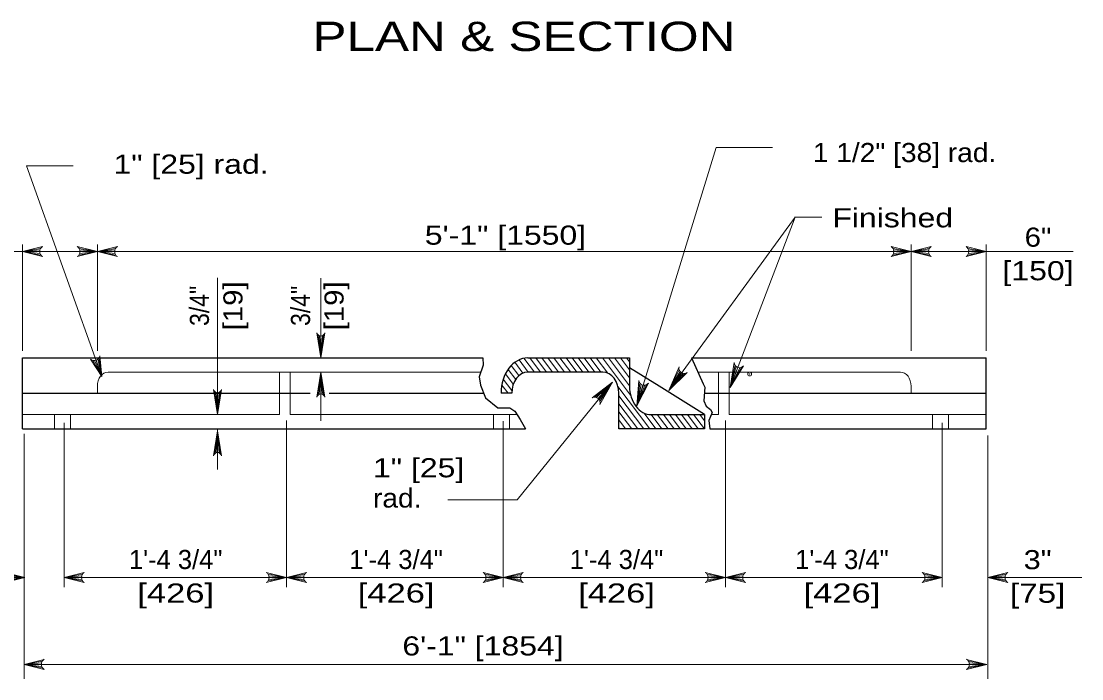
# Model space of a CAD drawing. Extents: x 1352.5 to 1386.5, y 735.9 to 779.9.
# Drawn here: x 1356.98 to 1365.64, y 745.48 to 750.85 of the extents above; entities that cross this region are included whole.
import ezdxf
from ezdxf.enums import TextEntityAlignment as Align

# ---------------------------------------------------------------- set-up
doc = ezdxf.new("R2010")
doc.units = 0
doc.header["$LTSCALE"] = 0.062
doc.header["$PDMODE"] = 32
doc.header["$PDSIZE"] = 0.031
doc.layers.add('1', color=7, linetype='Continuous', lineweight=13)

msp = doc.modelspace()

# ---------------------------------------------------------------- linework, layer by layer
at = {"layer": '1'}
for p, q in [((1362.27117, 747.83458), (1363.30317, 749.24783)), ((1356.99267, 748.15767), (1356.99267, 749.02575)), ((1357.60467, 748.15767), (1357.60467, 749.02575)), ((1364.24883, 748.15767), (1364.24883, 749.02575)), ((1364.86083, 748.15767), (1364.86083, 749.02575)), ((1357.14108, 748.99392), (1356.99267, 748.96792)), ((1357.136, 748.98108), (1356.99267, 748.96792)), ((1357.1345, 748.96792), (1356.99267, 748.96792)), ((1357.13717, 748.95125), (1356.99267, 748.96792)), ((1357.14283, 748.93925), (1356.99267, 748.96792)), ((1357.4545, 748.93925), (1357.60467, 748.96792)), ((1357.45625, 748.99392), (1357.60467, 748.96792)), ((1357.46017, 748.95125), (1357.60467, 748.96792)), ((1357.46125, 748.98108), (1357.60467, 748.96792)), ((1357.46275, 748.96792), (1357.60467, 748.96792)), ((1357.753, 748.99392), (1357.60467, 748.96792)), ((1357.748, 748.98108), (1357.60467, 748.96792)), ((1357.7465, 748.96792), (1357.60467, 748.96792)), ((1357.74908, 748.95125), (1357.60467, 748.96792)), ((1357.75475, 748.93925), (1357.60467, 748.96792)), ((1357.60467, 748.96792), (1359.55883, 748.96792)), ((1359.55883, 748.96792), (1361.28483, 748.96792)), ((1361.28483, 748.96792), (1362.64008, 748.96792)), ((1362.64008, 748.96792), (1364.24883, 748.96792)), ((1364.09867, 748.93925), (1364.24883, 748.96792)), ((1364.10042, 748.99392), (1364.24883, 748.96792)), ((1364.10433, 748.95125), (1364.24883, 748.96792)), ((1364.1055, 748.98108), (1364.24883, 748.96792)), ((1364.107, 748.96792), (1364.24883, 748.96792)), ((1364.39725, 748.99392), (1364.24883, 748.96792)), ((1364.39225, 748.98108), (1364.24883, 748.96792)), ((1364.24883, 748.96792), (1365.57108, 748.96792)), ((1364.39067, 748.96792), (1364.24883, 748.96792)), ((1364.39333, 748.95125), (1364.24883, 748.96792)), ((1364.399, 748.93925), (1364.24883, 748.96792)), ((1364.63833, 748.96792), (1364.86083, 748.96792)), ((1364.71067, 748.93925), (1364.86083, 748.96792)), ((1364.71242, 748.99392), (1364.86083, 748.96792)), ((1364.71633, 748.95125), (1364.86083, 748.96792)), ((1364.71742, 748.98108), (1364.86083, 748.96792)), ((1364.719, 748.96792), (1364.86083, 748.96792)), ((1358.58542, 748.75292), (1358.58542, 747.63708)), ((1359.42892, 748.09983), (1359.42892, 748.74983)), ((1359.40817, 748.28533), (1359.42892, 748.09983)), ((1359.41842, 748.27908), (1359.42892, 748.09983)), ((1359.45192, 748.28758), (1359.42892, 748.09983)), ((1359.44225, 748.28042), (1359.42892, 748.09983)), ((1359.42892, 748.27717), (1359.42892, 748.09983)), ((1357.567, 748.07975), (1357.64058, 747.94833)), ((1357.58075, 748.07925), (1357.64058, 747.94833)), ((1357.59367, 748.08217), (1357.64058, 747.94833)), ((1357.6085, 748.09017), (1357.64058, 747.94833)), ((1357.618, 748.0995), (1357.64058, 747.94833)), ((1361.01342, 748.06367), (1361.07958, 747.97617)), ((1361.04758, 748.08392), (1361.123, 747.98417)), ((1361.08742, 748.09675), (1361.1725, 747.98417)), ((1361.13442, 748.09983), (1361.22192, 747.98417)), ((1361.18392, 748.09983), (1361.27142, 747.98417)), ((1361.23333, 748.09983), (1361.32083, 747.98417)), ((1361.28283, 748.09983), (1361.37033, 747.98417)), ((1361.33233, 748.09983), (1361.41975, 747.98417)), ((1361.38175, 748.09983), (1361.46917, 747.98417)), ((1361.43117, 748.09983), (1361.51867, 747.98417)), ((1361.48067, 748.09983), (1361.56817, 747.98417)), ((1361.53008, 748.09983), (1361.61758, 747.98417)), ((1361.57958, 748.09983), (1361.667, 747.98417)), ((1361.629, 748.09983), (1361.7165, 747.98417)), ((1361.67842, 748.09983), (1361.77283, 747.975)), ((1361.728, 748.09983), (1361.95867, 747.7945)), ((1361.77733, 748.09983), (1361.9495, 747.872)), ((1361.82683, 748.09983), (1361.9495, 747.9375)), ((1361.87633, 748.09983), (1361.9495, 748.003)), ((1361.92575, 748.09983), (1361.9495, 748.06842)), ((1360.735, 747.98417), (1357.69208, 747.98417)), ((1359.09083, 747.63708), (1359.09083, 747.98417)), ((1359.17825, 747.63708), (1359.17825, 747.98417)), ((1359.406, 747.7965), (1359.42892, 747.98417)), ((1359.41558, 747.80358), (1359.42892, 747.98417)), ((1359.42892, 747.98417), (1359.42892, 747.58533)), ((1359.42892, 747.80683), (1359.42892, 747.98417)), ((1359.43942, 747.80492), (1359.42892, 747.98417)), ((1359.44975, 747.79867), (1359.42892, 747.98417)), ((1360.95808, 748.00617), (1361.02, 747.92417)), ((1360.98367, 748.03767), (1361.04625, 747.95483)), ((1362.355, 748.00208), (1362.27117, 747.83458)), ((1362.362, 747.98967), (1362.27117, 747.83458)), ((1362.37167, 747.98058), (1362.27117, 747.83458)), ((1362.38725, 747.97383), (1362.27117, 747.83458)), ((1362.40125, 747.97292), (1362.27117, 747.83458)), ((1364.16142, 747.98417), (1362.50875, 747.98417)), ((1362.67525, 747.63708), (1362.67525, 747.98417)), ((1362.76267, 747.63708), (1362.76267, 747.98417)), ((1362.8115, 748.03958), (1362.77, 747.85692)), ((1362.82125, 748.02917), (1362.77, 747.85692)), ((1362.83283, 748.02275), (1362.77, 747.85692)), ((1362.86333, 748.02233), (1362.77, 747.85692)), ((1362.84958, 748.01992), (1362.77, 747.85692)), ((1360.919, 747.92692), (1360.98917, 747.83408)), ((1360.93642, 747.96933), (1361.0005, 747.88458)), ((1361.6655, 747.77875), (1361.81117, 747.90058)), ((1361.67925, 747.77617), (1361.81117, 747.90058)), ((1361.69392, 747.76758), (1361.81117, 747.90058)), ((1361.7025, 747.7575), (1361.81117, 747.90058)), ((1361.70792, 747.74425), (1361.81117, 747.90058)), ((1362.03425, 747.89292), (1362.00858, 747.70742)), ((1357.60467, 747.8685), (1357.60467, 747.81058)), ((1358.56467, 747.82258), (1358.58542, 747.63708)), ((1358.57492, 747.81633), (1358.58542, 747.63708)), ((1358.60842, 747.82475), (1358.58542, 747.63708)), ((1358.59875, 747.81767), (1358.58542, 747.63708)), ((1358.58542, 747.81442), (1358.58542, 747.63708)), ((1360.90067, 747.82025), (1360.90792, 747.81058)), ((1360.9065, 747.878), (1360.95742, 747.81058)), ((1361.85517, 747.86608), (1362.11558, 747.52142)), ((1362.04483, 747.88342), (1362.00858, 747.70742)), ((1362.08742, 747.88017), (1362.00858, 747.70742)), ((1362.05692, 747.878), (1362.00858, 747.70742)), ((1362.07392, 747.87658), (1362.00858, 747.70742)), ((1364.24883, 747.8685), (1364.24883, 747.81058)), ((1361.86208, 747.79142), (1362.06608, 747.52142)), ((1361.86208, 747.726), (1362.01667, 747.52142)), ((1356.99267, 747.63708), (1359.09083, 747.63708)), ((1357.25492, 747.63708), (1357.25492, 747.52142)), ((1357.38608, 747.63708), (1357.38608, 747.52142)), ((1359.17825, 747.63708), (1361.03092, 747.63708)), ((1360.83933, 747.63708), (1360.83933, 747.52142)), ((1360.97042, 747.63708), (1360.97042, 747.52142)), ((1361.86208, 747.66058), (1361.96725, 747.52142)), ((1362.06842, 747.64925), (1362.165, 747.52142)), ((1362.12708, 747.63708), (1362.2145, 747.52142)), ((1362.1765, 747.63708), (1362.26392, 747.52142)), ((1362.226, 747.63708), (1362.31342, 747.52142)), ((1362.27542, 747.63708), (1362.36283, 747.52142)), ((1362.32483, 747.63708), (1362.41225, 747.52142)), ((1362.37433, 747.63708), (1362.46175, 747.52142)), ((1362.42383, 747.63708), (1362.51125, 747.52142)), ((1362.47325, 747.63708), (1362.56067, 747.52142)), ((1362.52275, 747.63708), (1362.5615, 747.58575)), ((1362.61733, 747.63708), (1362.67525, 747.63708)), ((1362.76267, 747.63708), (1364.86083, 747.63708)), ((1364.42367, 747.63708), (1364.42367, 747.52142)), ((1364.55483, 747.63708), (1364.55483, 747.52142)), ((1357.334, 746.22842), (1357.334, 747.57025)), ((1359.14808, 746.22842), (1359.14808, 747.5885)), ((1360.91842, 746.22842), (1360.91842, 747.58242)), ((1361.86208, 747.59517), (1361.91775, 747.52142)), ((1362.73242, 746.22842), (1362.73242, 747.5885)), ((1364.50275, 746.22842), (1364.50275, 747.57025)), ((1357.00617, 745.47992), (1357.00617, 747.47875)), ((1358.56467, 747.31983), (1358.58542, 747.50533)), ((1358.57492, 747.32608), (1358.58542, 747.50533)), ((1358.58542, 747.52142), (1358.58542, 747.18817)), ((1358.58542, 747.328), (1358.58542, 747.50533)), ((1358.59875, 747.32475), (1358.58542, 747.50533)), ((1358.60842, 747.31767), (1358.58542, 747.50533)), ((1361.86208, 747.52967), (1361.86833, 747.52142)), ((1364.87433, 745.47992), (1364.87433, 747.46658)), ((1356.86342, 746.333), (1357.01183, 746.30708)), ((1357.48242, 746.333), (1357.334, 746.30708)), ((1358.99967, 746.333), (1359.14808, 746.30708)), ((1359.2965, 746.333), (1359.14808, 746.30708)), ((1360.77, 746.333), (1360.91842, 746.30708)), ((1361.06683, 746.333), (1360.91842, 746.30708)), ((1362.58408, 746.333), (1362.73242, 746.30708)), ((1362.88083, 746.333), (1362.73242, 746.30708)), ((1364.35442, 746.333), (1364.50275, 746.30708)), ((1365.02275, 746.333), (1364.87433, 746.30708)), ((1356.24792, 746.30708), (1357.00283, 746.30708)), ((1356.86167, 746.27833), (1357.01183, 746.30708)), ((1356.86733, 746.29042), (1357.01183, 746.30708)), ((1356.86842, 746.32017), (1357.01183, 746.30708)), ((1356.87, 746.30708), (1357.01183, 746.30708)), ((1357.47742, 746.32017), (1357.334, 746.30708)), ((1357.47592, 746.30708), (1357.334, 746.30708)), ((1357.4785, 746.29042), (1357.334, 746.30708)), ((1357.48417, 746.27833), (1357.334, 746.30708)), ((1357.34392, 746.30708), (1364.09925, 746.30708)), ((1358.6425, 746.30708), (1359.14808, 746.30708)), ((1358.99792, 746.27833), (1359.14808, 746.30708)), ((1359.00358, 746.29042), (1359.14808, 746.30708)), ((1359.00467, 746.32017), (1359.14808, 746.30708)), ((1359.00625, 746.30708), (1359.14808, 746.30708)), ((1359.29142, 746.32017), (1359.14808, 746.30708)), ((1359.28992, 746.30708), (1359.14808, 746.30708)), ((1359.2925, 746.29042), (1359.14808, 746.30708)), ((1359.29825, 746.27833), (1359.14808, 746.30708)), ((1359.14808, 746.30708), (1359.50433, 746.30708)), ((1360.76825, 746.27833), (1360.91842, 746.30708)), ((1360.77392, 746.29042), (1360.91842, 746.30708)), ((1360.775, 746.32017), (1360.91842, 746.30708)), ((1360.77658, 746.30708), (1360.91842, 746.30708)), ((1361.06175, 746.32017), (1360.91842, 746.30708)), ((1361.06025, 746.30708), (1360.91842, 746.30708)), ((1361.06292, 746.29042), (1360.91842, 746.30708)), ((1361.06858, 746.27833), (1360.91842, 746.30708)), ((1362.58233, 746.27833), (1362.73242, 746.30708)), ((1362.588, 746.29042), (1362.73242, 746.30708)), ((1362.58908, 746.32017), (1362.73242, 746.30708)), ((1362.59058, 746.30708), (1362.73242, 746.30708)), ((1362.87583, 746.32017), (1362.73242, 746.30708)), ((1362.87433, 746.30708), (1362.73242, 746.30708)), ((1362.87692, 746.29042), (1362.73242, 746.30708)), ((1362.88258, 746.27833), (1362.73242, 746.30708)), ((1364.09925, 746.30708), (1364.50275, 746.30708)), ((1364.35267, 746.27833), (1364.50275, 746.30708)), ((1364.35833, 746.29042), (1364.50275, 746.30708)), ((1364.35942, 746.32017), (1364.50275, 746.30708)), ((1364.36092, 746.30708), (1364.50275, 746.30708)), ((1365.01775, 746.32017), (1364.87433, 746.30708)), ((1365.01617, 746.30708), (1364.87433, 746.30708)), ((1365.01883, 746.29042), (1364.87433, 746.30708)), ((1365.0245, 746.27833), (1364.87433, 746.30708)), ((1364.87433, 746.30708), (1365.64208, 746.30708)), ((1357.15458, 745.62367), (1357.00617, 745.59775)), ((1357.14958, 745.61083), (1357.00617, 745.59775)), ((1357.148, 745.59775), (1357.00617, 745.59775)), ((1357.15067, 745.58108), (1357.00617, 745.59775)), ((1357.15633, 745.56908), (1357.00617, 745.59775)), ((1357.00617, 745.59775), (1364.86592, 745.59775)), ((1364.71575, 745.56908), (1364.86592, 745.59775)), ((1364.7175, 745.62367), (1364.86592, 745.59775)), ((1364.72142, 745.58108), (1364.86592, 745.59775)), ((1364.7225, 745.61083), (1364.86592, 745.59775)), ((1364.724, 745.59775), (1364.86592, 745.59775))]:
    msp.add_line(p, q, dxfattribs=at)
at = {"layer": '1', "lineweight": 25}
for p, q in [((1356.99267, 747.52142), (1356.99267, 748.09983)), ((1362.45667, 748.09983), (1364.86083, 748.09983)), ((1364.86083, 747.52142), (1364.86083, 748.09983)), ((1361.731, 747.98417), (1361.119, 747.98417)), ((1356.99267, 747.81058), (1359.09083, 747.81058)), ((1358.98275, 747.81058), (1359.34183, 747.81058)), ((1359.49833, 747.81058), (1360.23017, 747.81058)), ((1360.21433, 747.81058), (1360.7585, 747.81058)), ((1360.98783, 747.81058), (1360.90042, 747.81058)), ((1362.56058, 747.81058), (1364.86083, 747.81058)), ((1356.99267, 747.52142), (1361.09958, 747.52142)), ((1362.60517, 747.52142), (1364.86083, 747.52142))]:
    msp.add_line(p, q, dxfattribs=at)
at = {"layer": '1'}
for points in [[(1362.00858, 747.70742), (1362.65642, 749.81892), (1363.11642, 749.81892)], [(1357.64058, 747.94833), (1357.02733, 749.66658), (1357.40617, 749.66658)], [(1362.77, 747.85692), (1363.30317, 749.24783), (1363.29642, 749.24783), (1363.51967, 749.24783)], [(1356.2885, 748.96792), (1357.37483, 748.96792), (1357.60467, 748.96792)], [(1357.15658, 748.92692), (1356.99267, 748.96792), (1357.15658, 749.00892)], [(1357.44075, 748.92692), (1357.60467, 748.96792), (1357.44075, 749.00892)], [(1357.76858, 748.92692), (1357.60467, 748.96792), (1357.76858, 749.00892)], [(1364.08492, 748.92692), (1364.24883, 748.96792), (1364.08492, 749.00892)], [(1364.41275, 748.92692), (1364.24883, 748.96792), (1364.41275, 749.00892)], [(1364.69692, 748.92692), (1364.86083, 748.96792), (1364.69692, 749.00892)], [(1359.46175, 748.30475), (1359.42892, 748.09983), (1359.39617, 748.30475)], [(1357.625, 748.11658), (1357.64058, 747.94833), (1357.54767, 748.08942)], [(1362.88092, 748.034), (1362.77, 747.85692), (1362.80433, 748.06308)], [(1359.39617, 747.77925), (1359.42892, 747.98417), (1359.46175, 747.77925)], [(1362.42108, 747.98008), (1362.27117, 747.83458), (1362.35358, 748.02658)], [(1361.81117, 747.90058), (1361.03267, 746.941), (1360.46567, 746.941)], [(1361.64492, 747.774), (1361.81117, 747.90058), (1361.70642, 747.71975)], [(1362.10392, 747.89333), (1362.00858, 747.70742), (1362.02508, 747.91567)], [(1358.61825, 747.842), (1358.58542, 747.63708), (1358.55267, 747.842)], [(1358.61825, 747.30042), (1358.58542, 747.50533), (1358.55267, 747.30042)], [(1356.84792, 746.26608), (1357.01183, 746.30708), (1356.84792, 746.348)], [(1357.49792, 746.26608), (1357.334, 746.30708), (1357.49792, 746.348)], [(1358.98417, 746.26608), (1359.14808, 746.30708), (1358.98417, 746.348)], [(1359.312, 746.26608), (1359.14808, 746.30708), (1359.312, 746.348)], [(1360.7545, 746.26608), (1360.91842, 746.30708), (1360.7545, 746.348)], [(1361.08233, 746.26608), (1360.91842, 746.30708), (1361.08233, 746.348)], [(1362.5685, 746.26608), (1362.73242, 746.30708), (1362.5685, 746.348)], [(1362.89642, 746.26608), (1362.73242, 746.30708), (1362.89642, 746.348)], [(1364.33883, 746.26608), (1364.50275, 746.30708), (1364.33883, 746.348)], [(1365.03825, 746.26608), (1364.87433, 746.30708), (1365.03825, 746.348)], [(1360.3695, 746.30708), (1360.91842, 746.30708), (1361.36467, 746.30708)], [(1362.30608, 746.30708), (1362.73242, 746.30708), (1363.15783, 746.30708)], [(1357.17008, 745.55675), (1357.00617, 745.59775), (1357.17008, 745.63875)], [(1364.702, 745.55675), (1364.86592, 745.59775), (1364.702, 745.63875)]]:
    msp.add_lwpolyline(points, dxfattribs=at)
at = {"layer": '1', "lineweight": 25}
for points in [[(1356.99267, 748.09983), (1357.603, 748.09983), (1360.75192, 748.09983)], [(1360.75192, 748.09983), (1360.75375, 748.04092), (1360.72242, 747.946), (1360.73333, 747.87767), (1360.7725, 747.77333), (1360.87375, 747.691), (1360.97233, 747.69258), (1361.01325, 747.6655), (1361.05592, 747.597), (1361.09958, 747.52142)], [(1361.119, 748.09983), (1361.9495, 748.09983), (1361.9495, 747.8685)], [(1362.45667, 748.09983), (1362.552, 747.88792), (1362.56383, 747.85992), (1362.55675, 747.75025), (1362.57575, 747.7065), (1362.60975, 747.67833), (1362.62408, 747.65358), (1362.598, 747.58992), (1362.60517, 747.52142)], [(1362.5615, 747.63708), (1362.19158, 747.86775), (1361.9495, 748.01867)], [(1362.12433, 747.63708), (1362.5615, 747.63708), (1362.5615, 747.52142), (1361.86208, 747.52142), (1361.86208, 747.81058)]]:
    msp.add_lwpolyline(points, dxfattribs=at)
at = {"layer": '1'}
for centre, start, end in [((1362.84844, 748.06404), 181.33394, 317.16007), ((1362.3967, 748.017), 167.53484, 303.36097), ((1362.06896, 747.92045), 186.24931, 322.07544), ((1361.66475, 747.73444), 340.68416, 116.51028)]:
    msp.add_arc(centre, 0.04422, start, end, dxfattribs=at)
for centre, major_axis, ratio, start_param, end_param in [((1357.16982, 748.96798), (0, 0.04422), 0.8, 0.3855052, 2.7561184), ((1357.42747, 748.96798), (0, 0.04422), 0.8, 3.5270669, 5.8976801), ((1357.78178, 748.96798), (0, 0.04422), 0.8, 0.3855052, 2.7561184), ((1364.07168, 748.96798), (0, 0.04422), 0.8, 3.5270669, 5.8976801), ((1364.426, 748.96798), (0, 0.04422), 0.8, 0.3855052, 2.7561184), ((1364.68365, 748.96798), (0, 0.04422), 0.8, 3.5270669, 5.8976801), ((1359.42891, 748.3213), (0, -0.04422), 0.8, 5.0978942, 7.4685073), ((1357.58192, 748.11545), (-0.04173, -0.01464), 0.8, 0.3855052, 2.7561184), ((1357.69205, 747.86847), (0, 0.1157), 0.755635, 0, 1.5707963), ((1364.16141, 747.86847), (0, 0.1157), 0.755635, 4.712389, 6.2831853), ((1358.5854, 747.85852), (0, -0.04422), 0.8, 5.0978942, 7.4685073), ((1359.42898, 747.76272), (0, 0.04422), 0.8, 5.0978942, 7.4685073), ((1358.5854, 747.28389), (0, 0.04422), 0.8, 5.0978633, 7.4684764), ((1357.51119, 746.30709), (0, 0.04422), 0.8, 0.3855052, 2.7561184), ((1358.97092, 746.30709), (0, 0.04422), 0.8, 3.5270669, 5.8976801), ((1359.32523, 746.30709), (0, 0.04422), 0.8, 0.3855052, 2.7561184), ((1360.74125, 746.30709), (0, 0.04422), 0.8, 3.5270669, 5.8976801), ((1361.09556, 746.30709), (0, 0.04422), 0.8, 0.3855052, 2.7561184), ((1362.55529, 746.30709), (0, 0.04422), 0.8, 3.5270669, 5.8976801), ((1362.90961, 746.30709), (0, 0.04422), 0.8, 0.3855052, 2.7561184), ((1364.32563, 746.30709), (0, 0.04422), 0.8, 3.5270669, 5.8976801), ((1365.05149, 746.30709), (0, 0.04422), 0.8, 0.3855052, 2.7561184), ((1357.18335, 745.5978), (0, 0.04422), 0.8, 0.3855052, 2.7561184), ((1364.68873, 745.5978), (0, 0.04422), 0.8, 3.5270669, 5.8976801)]:
    msp.add_ellipse(centre, major_axis=major_axis, ratio=ratio, start_param=start_param, end_param=end_param, dxfattribs=at)
at = {"layer": '1', "lineweight": 25}
for centre, major_axis, start_param, end_param in [((1361.11899, 747.81062), (0, 0.28924), 0, 1.5707963), ((1361.11899, 747.81062), (0, 0.17354), 6.2831853, 7.8539816), ((1361.73096, 747.81062), (0, 0.17354), 4.712389, 6.2831853), ((1362.12437, 747.86847), (0, 0.23139), 1.5707963, 3.1415927)]:
    msp.add_ellipse(centre, major_axis=major_axis, ratio=0.755635, start_param=start_param, end_param=end_param, dxfattribs=at)
at = {"layer": '1'}
msp.add_point((1362.93042, 747.96825), dxfattribs=at)

# ---------------------------------------------------------------- texts
for s, height, width, p in [('PLAN & SECTION', 0.24, 1.3, (1359.36083, 750.60508)), ('Finished', 0.156, 1.25, (1363.6055, 749.16575)), ('5\'-1" [1550]', 0.156, 1.25, (1360.27817, 749.02408)), ('1" [25]', 0.156, 1.25, (1359.85525, 747.12492)), ('rad.', 0.156, 1.1, (1359.85525, 746.87783)), ('6\'-1" [1854]', 0.156, 1.25, (1360.09492, 745.67033))]:
    msp.add_text(s, height=height, dxfattribs=dict(at, width=width)).set_placement(p)
for s, width, p in [('1 1/2" [38] rad.', 1.1, (1364.19487, 749.6985)), ('1" [25] rad.', 1.25, (1358.36967, 749.60342)), ('6"', 1.15, (1365.28475, 749.00767)), ('[150]', 1.25, (1365.28475, 748.73367)), ('3"', 1.2, (1365.28146, 746.37458)), ('[426]', 1.35, (1358.24429, 746.10208)), ('[426]', 1.35, (1360.04396, 746.10208)), ('[426]', 1.35, (1361.84362, 746.10208)), ('[426]', 1.35, (1363.68387, 746.10208)), ('[75]', 1.3, (1365.28146, 746.10058))]:
    msp.add_text(s, height=0.156, dxfattribs=dict(at, width=width)).set_placement(p, align=Align.CENTER)
for s, width, p in [('3/4"', 0.9, (1358.51567, 748.52458)), ('[19]', 1.15, (1358.78967, 748.52454)), ('3/4"', 0.9, (1359.34108, 748.52458)), ('[19]', 1.15, (1359.61508, 748.52454))]:
    msp.add_text(s, height=0.156, rotation=90, dxfattribs=dict(at, width=width)).set_placement(p, align=Align.CENTER)
for p in [(1358.24429, 746.37608), (1360.04396, 746.37608), (1361.84362, 746.37608), (1363.68387, 746.37608)]:
    msp.add_text('1\'-4 3/4"', height=0.156, dxfattribs=at).set_placement(p, align=Align.CENTER)

doc.saveas('drawing.dxf')
